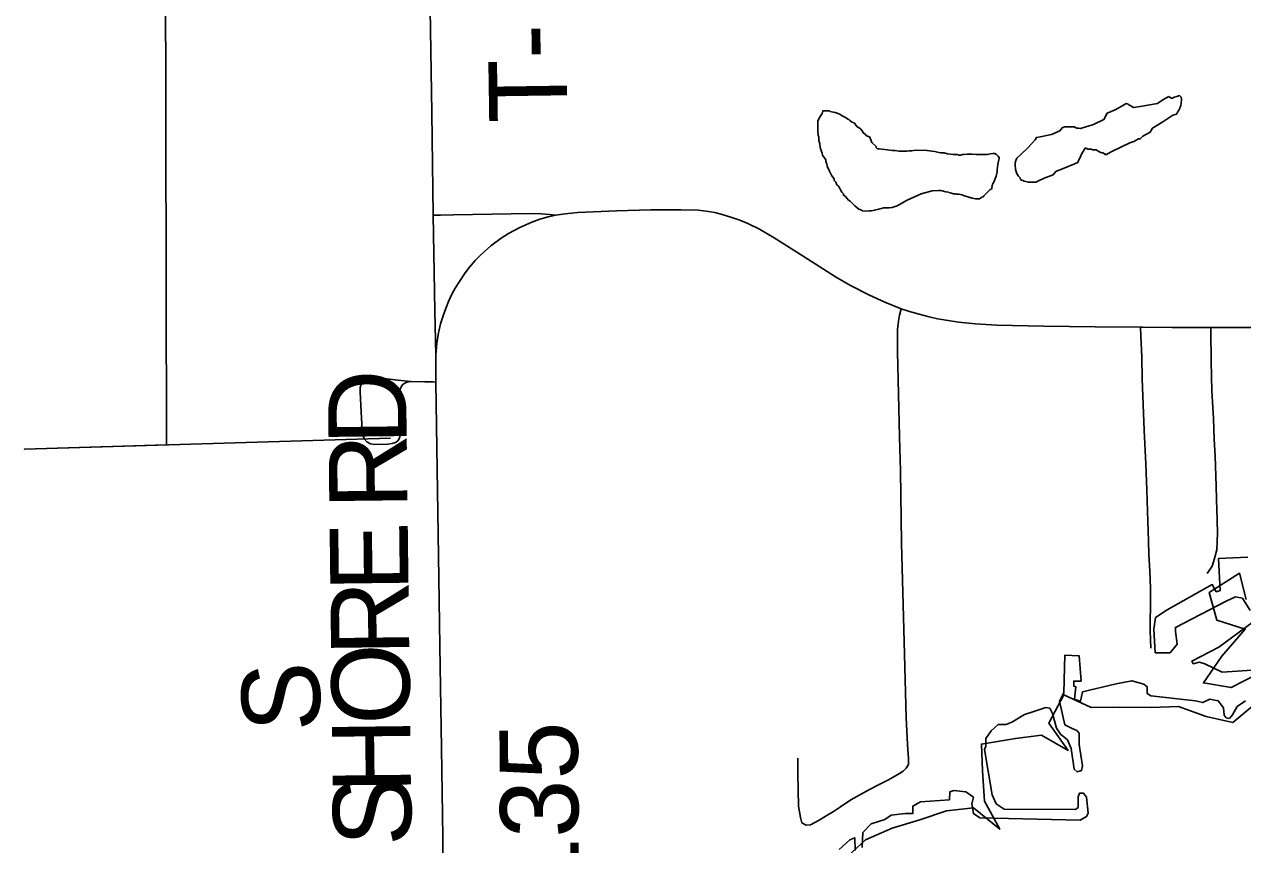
# Model space of a CAD drawing. Extents: x 0 to 34, y 0 to 22.
# Drawn here: x 8.1053 to 8.5479, y 18.1919 to 18.4901 of the extents above; entities that cross this region are included whole.
import ezdxf

# ---------------------------------------------------------------- set-up
doc = ezdxf.new("R2010")
doc.units = 0
for name, color, linetype in [('GM_X_Corporation', 7, 'Continuous'), ('GM_X_County_Road', 7, 'Continuous'), ('GM_X_County_Road_Text', 7, 'Continuous'), ('GM_X_Major_Lake', 7, 'Continuous'), ('GM_X_Minor_River', 7, 'Continuous'), ('GM_X_State_Route', 7, 'Continuous'), ('GM_X_Township_Road', 7, 'Continuous'), ('GM_X_Township_Road_Text', 7, 'Continuous')]:
    doc.layers.add(name, color=color, linetype=linetype)

msp = doc.modelspace()

# ---------------------------------------------------------------- linework, layer by layer
at = {"layer": 'GM_X_Corporation'}
for points in [[(8.55064, 18.27699), (8.54776, 18.28154), (8.54524, 18.28202), (8.54189, 18.28046), (8.52343, 18.27088), (8.52343, 18.26944), (8.52403, 18.26476), (8.52151, 18.26165), (8.51612, 18.26165), (8.51564, 18.27028), (8.51624, 18.27447), (8.52043, 18.27723), (8.53685, 18.28646), (8.53829, 18.28382), (8.53973, 18.2843), (8.53913, 18.29592), (8.5498, 18.2964)], [(8.55315, 18.25542), (8.54045, 18.25458), (8.5341, 18.25769), (8.53218, 18.25829), (8.5299, 18.25769), (8.52942, 18.25865), (8.53925, 18.26369), (8.55171, 18.27291)], [(8.4097, 18.19082), (8.40994, 18.19633), (8.41293, 18.19945), (8.41785, 18.20101), (8.42024, 18.20268), (8.42528, 18.20328), (8.42803, 18.20317), (8.42803, 18.20592), (8.43079, 18.20748), (8.44134, 18.2082), (8.44146, 18.21108), (8.4429, 18.21155), (8.44733, 18.21108), (8.45009, 18.20916), (8.44949, 18.20676), (8.45009, 18.20317), (8.45236, 18.20161), (8.48879, 18.20077), (8.49119, 18.20209), (8.49179, 18.2034), (8.49119, 18.20916), (8.49011, 18.21059), (8.48855, 18.21059), (8.48808, 18.20928), (8.48808, 18.20544), (8.48712, 18.20472), (8.46123, 18.20484), (8.45836, 18.20676), (8.45692, 18.20999), (8.45404, 18.22653), (8.45452, 18.22773), (8.45452, 18.23049), (8.45656, 18.23325), (8.45907, 18.23564), (8.46195, 18.23564), (8.46423, 18.2366), (8.46866, 18.23924), (8.4713, 18.24008), (8.47633, 18.24176), (8.47777, 18.24151), (8.47885, 18.23956), (8.48029, 18.2342), (8.48173, 18.23205), (8.48424, 18.23001), (8.48556, 18.22689), (8.48664, 18.21934), (8.48772, 18.21839), (8.48939, 18.21886), (8.48975, 18.22054), (8.48844, 18.22833), (8.48844, 18.23241), (8.4876, 18.23336), (8.48592, 18.23408), (8.48328, 18.2354), (8.48128, 18.24409), (8.48292, 18.24715), (8.48328, 18.26081), (8.48844, 18.26057), (8.48915, 18.25134), (8.48652, 18.25134), (8.48652, 18.24954), (8.48724, 18.24931), (8.48676, 18.24475), (8.4876, 18.24439), (8.48891, 18.24403), (8.48975, 18.24751), (8.50198, 18.25038), (8.50761, 18.25146), (8.51192, 18.25026), (8.51324, 18.24931), (8.51324, 18.24679), (8.51456, 18.24595), (8.53074, 18.24415), (8.53338, 18.24355), (8.53601, 18.24475), (8.53901, 18.24415), (8.54093, 18.24163), (8.54117, 18.239), (8.54189, 18.23804), (8.54309, 18.2378), (8.54416, 18.23912), (8.54584, 18.24211), (8.54896, 18.24415)], [(8.40131, 18.1901), (8.40514, 18.1937), (8.40694, 18.19442), (8.40706, 18.18974)]]:
    msp.add_lwpolyline(points, dxfattribs=at)
at = {"layer": 'GM_X_County_Road'}
for points in [[(8.25479, 18.36008), (8.25478, 18.36451), (8.25479, 18.36978)], [(8.2575, 18.17059), (8.25731, 18.19468), (8.25689, 18.22692), (8.25625, 18.26405), (8.25588, 18.28884), (8.25479, 18.36008)]]:
    msp.add_lwpolyline(points, dxfattribs=at)
at = {"layer": 'GM_X_Major_Lake'}
for points in [[(8.54918, 18.28107), (8.54671, 18.29057), (8.53571, 18.28354), (8.53855, 18.27347), (8.5488, 18.27024), (8.54026, 18.26037), (8.53362, 18.25068), (8.54368, 18.24897), (8.55317, 18.25391)], [(8.54918, 18.28107), (8.54671, 18.29057), (8.53571, 18.28354), (8.53855, 18.27347), (8.5488, 18.27024), (8.54026, 18.26037), (8.53362, 18.25068), (8.54368, 18.24897), (8.55317, 18.25391)], [(8.55374, 18.24422), (8.54425, 18.23625), (8.53457, 18.23853), (8.52452, 18.24213), (8.51465, 18.24175), (8.50326, 18.24194), (8.49283, 18.24175), (8.48296, 18.24631), (8.47746, 18.23605), (8.48448, 18.22618), (8.4748, 18.23168), (8.46532, 18.23054), (8.45298, 18.22845), (8.45336, 18.21877), (8.45412, 18.20775), (8.45962, 18.19749), (8.45014, 18.20528), (8.44027, 18.20414)], [(8.55374, 18.24422), (8.54425, 18.23625), (8.53457, 18.23853), (8.52452, 18.24213), (8.51465, 18.24175), (8.50326, 18.24194), (8.49283, 18.24175), (8.48296, 18.24631), (8.47746, 18.23605), (8.48448, 18.22618), (8.4748, 18.23168), (8.46532, 18.23054), (8.45298, 18.22845), (8.45336, 18.21877), (8.45412, 18.20775), (8.45962, 18.19749), (8.45014, 18.20528), (8.44027, 18.20414)], [(8.44027, 18.20414), (8.43059, 18.20091), (8.42054, 18.19787), (8.41086, 18.19369), (8.40137, 18.18495)]]:
    msp.add_lwpolyline(points, dxfattribs=at)
at = {"layer": 'GM_X_Minor_River'}
for points in [[(8.18599, 18.63264), (8.18437, 18.57885), (8.15649, 18.57188), (8.15692, 18.33718), (8.10529, 18.33561), (8.23835, 18.33965)], [(8.52105, 18.46387), (8.51883, 18.46259), (8.51692, 18.46128), (8.51064, 18.46023), (8.50817, 18.45989), (8.50723, 18.46047), (8.50648, 18.46086), (8.5063, 18.46105), (8.50554, 18.46126), (8.50458, 18.4607), (8.50153, 18.45903), (8.49866, 18.45775), (8.49749, 18.45548), (8.49367, 18.45364), (8.48891, 18.45219), (8.48816, 18.45239), (8.48759, 18.4524), (8.48665, 18.45279), (8.48323, 18.45284), (8.48228, 18.45247), (8.4815, 18.45134), (8.47845, 18.45006), (8.47427, 18.44917), (8.47294, 18.449), (8.47254, 18.44805), (8.46966, 18.44505), (8.46735, 18.44281), (8.46581, 18.4415), (8.46542, 18.44056), (8.46522, 18.4398), (8.46521, 18.43904), (8.46537, 18.43733), (8.46555, 18.43657), (8.46573, 18.43619), (8.46573, 18.436), (8.46647, 18.43485), (8.46703, 18.43427), (8.46721, 18.4337), (8.46853, 18.43311), (8.47004, 18.43271), (8.47289, 18.43267), (8.47346, 18.43304), (8.47575, 18.43414), (8.479, 18.43543), (8.47996, 18.43655), (8.48454, 18.43839), (8.48797, 18.43986), (8.48836, 18.4408), (8.48895, 18.44193), (8.48934, 18.44288), (8.4907, 18.44514), (8.49108, 18.44513), (8.49165, 18.44474), (8.49297, 18.44472), (8.49335, 18.44453), (8.49392, 18.44452), (8.49468, 18.44451), (8.49543, 18.44393), (8.49637, 18.44354), (8.49674, 18.44334), (8.49712, 18.44334), (8.49788, 18.44295), (8.49787, 18.44275), (8.49844, 18.44275), (8.49902, 18.44312), (8.50035, 18.44386), (8.50685, 18.44699), (8.50837, 18.44754), (8.51009, 18.44847), (8.51066, 18.44846), (8.51162, 18.4494), (8.5143, 18.45088), (8.51508, 18.45238), (8.5189, 18.45461), (8.52254, 18.45703), (8.52387, 18.45739), (8.52407, 18.45795), (8.52465, 18.45889), (8.52504, 18.45965), (8.52544, 18.46059), (8.52566, 18.46249), (8.52566, 18.46306), (8.52548, 18.46363), (8.52492, 18.46421), (8.52397, 18.46384), (8.52302, 18.46367), (8.52244, 18.46329), (8.52188, 18.4633), (8.52105, 18.46387)], [(8.52105, 18.46387), (8.51883, 18.46259), (8.51692, 18.46128), (8.51064, 18.46023), (8.50817, 18.45989), (8.50723, 18.46047), (8.50648, 18.46086), (8.5063, 18.46105), (8.50554, 18.46126), (8.50458, 18.4607), (8.50153, 18.45903), (8.49866, 18.45775), (8.49749, 18.45548), (8.49367, 18.45364), (8.48891, 18.45219), (8.48816, 18.45239), (8.48759, 18.4524), (8.48665, 18.45279), (8.48323, 18.45284), (8.48228, 18.45247), (8.4815, 18.45134), (8.47845, 18.45006), (8.47427, 18.44917), (8.47294, 18.449), (8.47254, 18.44805), (8.46966, 18.44505), (8.46735, 18.44281), (8.46581, 18.4415), (8.46542, 18.44056), (8.46522, 18.4398), (8.46521, 18.43904), (8.46537, 18.43733), (8.46555, 18.43657), (8.46573, 18.43619), (8.46573, 18.436), (8.46647, 18.43485), (8.46703, 18.43427), (8.46721, 18.4337), (8.46853, 18.43311), (8.47004, 18.43271), (8.47289, 18.43267), (8.47346, 18.43304), (8.47575, 18.43414), (8.479, 18.43543), (8.47996, 18.43655)], [(8.47996, 18.43655), (8.48454, 18.43839), (8.48797, 18.43986), (8.48836, 18.4408), (8.48895, 18.44193), (8.48934, 18.44288), (8.4907, 18.44514), (8.49108, 18.44513), (8.49165, 18.44474), (8.49297, 18.44472), (8.49335, 18.44453), (8.49392, 18.44452), (8.49468, 18.44451), (8.49543, 18.44393), (8.49637, 18.44354), (8.49674, 18.44334), (8.49712, 18.44334), (8.49788, 18.44295), (8.49787, 18.44275), (8.49844, 18.44275), (8.49902, 18.44312), (8.50035, 18.44386), (8.50685, 18.44699), (8.50837, 18.44754), (8.51009, 18.44847), (8.51066, 18.44846), (8.51162, 18.4494), (8.5143, 18.45088), (8.51508, 18.45238), (8.5189, 18.45461), (8.52254, 18.45703), (8.52387, 18.45739), (8.52407, 18.45795), (8.52465, 18.45889), (8.52504, 18.45965), (8.52544, 18.46059), (8.52566, 18.46249), (8.52566, 18.46306), (8.52548, 18.46363), (8.52492, 18.46421), (8.52397, 18.46384), (8.52302, 18.46367), (8.52244, 18.46329), (8.52188, 18.4633), (8.52105, 18.46387)], [(8.45521, 18.44279), (8.44953, 18.44287), (8.44782, 18.4429), (8.44668, 18.44272), (8.44611, 18.44273), (8.44535, 18.44255), (8.44478, 18.44256), (8.44422, 18.44276), (8.4427, 18.44278), (8.44062, 18.443), (8.43949, 18.44339), (8.43816, 18.44341), (8.43702, 18.44362), (8.43608, 18.44382), (8.43495, 18.44403), (8.43324, 18.44424), (8.42907, 18.4443), (8.42774, 18.44413), (8.42679, 18.44414), (8.42584, 18.44397), (8.423, 18.44401), (8.42168, 18.44422), (8.42054, 18.44423), (8.41884, 18.44445), (8.41581, 18.44487), (8.41524, 18.44488), (8.41468, 18.44527), (8.41468, 18.44565), (8.41319, 18.44719), (8.41246, 18.4491), (8.41114, 18.44968), (8.41058, 18.45026), (8.41002, 18.45065), (8.40983, 18.45122), (8.4089, 18.45218), (8.40777, 18.45296), (8.40684, 18.45411), (8.40572, 18.4547), (8.40515, 18.45509), (8.40478, 18.45547), (8.4044, 18.45567), (8.40384, 18.45605), (8.40233, 18.45684), (8.40158, 18.45742), (8.39989, 18.45801), (8.39913, 18.45821), (8.398, 18.45842), (8.39781, 18.45861), (8.3961, 18.45863), (8.39535, 18.45864), (8.39514, 18.4577), (8.39417, 18.45619), (8.39358, 18.45487), (8.39352, 18.45088), (8.39371, 18.45031), (8.3937, 18.44974), (8.39388, 18.44917), (8.39386, 18.44784), (8.39422, 18.4467), (8.39439, 18.44537), (8.39475, 18.44422), (8.39512, 18.44327), (8.3953, 18.4425), (8.39585, 18.44174), (8.39623, 18.44116), (8.39641, 18.44078), (8.3964, 18.44021), (8.39677, 18.43926), (8.39694, 18.43849), (8.39749, 18.43716), (8.39805, 18.4362), (8.3986, 18.43505), (8.39953, 18.4339), (8.39952, 18.43333), (8.40008, 18.43275), (8.40045, 18.4318), (8.40101, 18.43122), (8.40138, 18.43064), (8.40175, 18.42988), (8.4023, 18.42911), (8.40286, 18.42854), (8.40286, 18.42797), (8.40342, 18.42758), (8.40473, 18.42623), (8.40529, 18.42584), (8.40697, 18.42411), (8.40847, 18.42295), (8.40941, 18.42255), (8.40979, 18.42236), (8.4113, 18.42215), (8.41225, 18.42232), (8.41301, 18.42231), (8.41415, 18.42249), (8.41567, 18.42285), (8.41758, 18.42339), (8.41947, 18.42336)], [(8.45114, 18.4426), (8.45521, 18.44279), (8.44953, 18.44287), (8.44782, 18.4429), (8.44668, 18.44272), (8.44611, 18.44273), (8.44535, 18.44255), (8.44478, 18.44256), (8.44422, 18.44276), (8.4427, 18.44278), (8.44062, 18.443), (8.43949, 18.44339), (8.43816, 18.44341), (8.43702, 18.44362), (8.43608, 18.44382), (8.43495, 18.44403), (8.43324, 18.44424), (8.42907, 18.4443), (8.42774, 18.44413), (8.42679, 18.44414), (8.42584, 18.44397), (8.423, 18.44401), (8.42168, 18.44422), (8.42054, 18.44423), (8.41884, 18.44445), (8.41581, 18.44487), (8.41524, 18.44488), (8.41468, 18.44527), (8.41468, 18.44565), (8.41319, 18.44719), (8.41246, 18.4491), (8.41114, 18.44968), (8.41058, 18.45026), (8.41002, 18.45065), (8.40983, 18.45122), (8.4089, 18.45218), (8.40777, 18.45296), (8.40684, 18.45411), (8.40572, 18.4547), (8.40515, 18.45509), (8.40478, 18.45547), (8.4044, 18.45567), (8.40384, 18.45605), (8.40233, 18.45684), (8.40158, 18.45742), (8.39989, 18.45801), (8.39913, 18.45821), (8.398, 18.45842), (8.39781, 18.45861), (8.3961, 18.45863), (8.39535, 18.45864), (8.39514, 18.4577), (8.39417, 18.45619), (8.39358, 18.45487), (8.39352, 18.45088), (8.39371, 18.45031), (8.3937, 18.44974), (8.39388, 18.44917), (8.39386, 18.44784), (8.39422, 18.4467), (8.39439, 18.44537), (8.39475, 18.44422), (8.39512, 18.44327), (8.3953, 18.4425), (8.39585, 18.44174), (8.39623, 18.44116), (8.39641, 18.44078), (8.3964, 18.44021), (8.39677, 18.43926), (8.39694, 18.43849), (8.39749, 18.43716), (8.39805, 18.4362), (8.3986, 18.43505), (8.39953, 18.4339), (8.39952, 18.43333), (8.40008, 18.43275), (8.40045, 18.4318), (8.40101, 18.43122), (8.40138, 18.43064), (8.40175, 18.42988), (8.4023, 18.42911), (8.40286, 18.42854), (8.40286, 18.42797), (8.40342, 18.42758), (8.40473, 18.42623), (8.40529, 18.42584), (8.40697, 18.42411), (8.40847, 18.42295), (8.40941, 18.42255), (8.40979, 18.42236), (8.4113, 18.42215), (8.41225, 18.42232), (8.41301, 18.42231), (8.41415, 18.42249), (8.41567, 18.42285), (8.41758, 18.42339), (8.41947, 18.42336)], [(8.41947, 18.42336), (8.42061, 18.42354), (8.42233, 18.42408), (8.42596, 18.42612), (8.43111, 18.42851), (8.43511, 18.4296), (8.43739, 18.42975), (8.43815, 18.42974), (8.43871, 18.42954), (8.44004, 18.42915), (8.44098, 18.42913), (8.44117, 18.42894), (8.44211, 18.42874), (8.44287, 18.42854), (8.44344, 18.42853), (8.44381, 18.42833), (8.44495, 18.42832), (8.4459, 18.42811), (8.44646, 18.42792), (8.44835, 18.42732), (8.44854, 18.42713), (8.44892, 18.42712), (8.44967, 18.42692), (8.4508, 18.42671), (8.45232, 18.42669), (8.45309, 18.42725), (8.45366, 18.42743), (8.45386, 18.42781), (8.45616, 18.43006), (8.45673, 18.43024), (8.45674, 18.43081), (8.45695, 18.43194), (8.45753, 18.4327), (8.45832, 18.43496), (8.45872, 18.43648), (8.45873, 18.43723), (8.45895, 18.43913), (8.45916, 18.44046), (8.45935, 18.44064), (8.45937, 18.44159), (8.459, 18.44217), (8.45844, 18.44275), (8.45787, 18.44313), (8.45711, 18.44314), (8.45616, 18.44297), (8.45521, 18.44279)]]:
    msp.add_lwpolyline(points, dxfattribs=at)
at = {"layer": 'GM_X_State_Route'}
msp.add_lwpolyline([(8.55772, 18.37993), (8.53627, 18.37991), (8.52231, 18.3799), (8.51144, 18.38004), (8.51078, 18.38004), (8.49433, 18.38013), (8.47569, 18.38037), (8.4586, 18.38079), (8.45086, 18.38123), (8.44469, 18.38182), (8.44011, 18.3825), (8.43697, 18.3831), (8.43404, 18.38375), (8.43038, 18.38468), (8.42679, 18.38574), (8.42385, 18.38672), (8.41791, 18.38906), (8.41226, 18.39163), (8.40539, 18.3952), (8.40001, 18.39828), (8.38693, 18.40665), (8.37771, 18.41246), (8.37232, 18.4156), (8.36813, 18.41772), (8.36523, 18.41892), (8.36233, 18.4199), (8.35881, 18.42098), (8.3561, 18.42166), (8.35294, 18.4222), (8.3501, 18.42251), (8.34373, 18.42272), (8.33283, 18.42272), (8.3204, 18.42236), (8.30641, 18.4217), (8.30174, 18.42127), (8.29835, 18.42072), (8.29559, 18.42011), (8.29257, 18.41924), (8.28962, 18.41818), (8.28531, 18.41629), (8.28119, 18.41404), (8.27855, 18.41234), (8.27478, 18.40953), (8.27123, 18.40644), (8.26902, 18.40421), (8.26699, 18.40181), (8.26543, 18.39971), (8.26331, 18.39662), (8.26185, 18.39418), (8.26064, 18.39196), (8.25939, 18.3893), (8.25852, 18.38711), (8.25738, 18.38415), (8.2565, 18.38118), (8.25577, 18.37796), (8.25516, 18.37422), (8.25479, 18.36978)], dxfattribs=at)
at = {"layer": 'GM_X_Township_Road'}
for points in [[(8.25381, 18.4207), (8.25335, 18.45797), (8.25249, 18.51077), (8.25217, 18.52319), (8.25219, 18.52784), (8.25145, 18.57598), (8.25088, 18.61014), (8.24998, 18.65828), (8.24985, 18.66722)], [(8.25381, 18.4207), (8.25644, 18.42076), (8.26114, 18.42082), (8.28901, 18.42138), (8.29305, 18.4212), (8.29605, 18.42097), (8.29835, 18.42072)], [(8.25479, 18.36978), (8.2544, 18.3859), (8.25381, 18.4207)], [(8.38623, 18.22332), (8.38623, 18.21774), (8.38658, 18.20591), (8.38719, 18.20182), (8.38775, 18.19981), (8.38928, 18.19904), (8.39084, 18.19912), (8.39241, 18.19991), (8.39398, 18.20078), (8.39655, 18.20236), (8.3992, 18.20392), (8.40174, 18.20564), (8.40557, 18.20823), (8.41229, 18.21199), (8.41505, 18.21339), (8.41919, 18.21544), (8.42323, 18.21775), (8.42451, 18.21864), (8.42566, 18.2197), (8.42646, 18.22098), (8.42651, 18.22306), (8.42608, 18.22828), (8.42564, 18.23811), (8.42545, 18.2472), (8.42504, 18.26114), (8.42393, 18.30144), (8.42359, 18.32778), (8.42326, 18.34017), (8.42289, 18.35567), (8.4225, 18.37117), (8.42246, 18.37581), (8.42251, 18.37918), (8.42284, 18.38224), (8.4232, 18.3844), (8.42385, 18.38672)], [(8.51457, 18.26333), (8.51431, 18.26959), (8.51444, 18.28208), (8.51435, 18.28518), (8.51414, 18.29135), (8.51385, 18.29752), (8.51367, 18.30218), (8.51334, 18.31307), (8.51306, 18.32085), (8.51266, 18.33017), (8.51206, 18.34258), (8.51182, 18.34881), (8.51143, 18.36129), (8.5112, 18.36908), (8.5109, 18.37686), (8.51078, 18.38004)], [(8.535, 18.29049), (8.53674, 18.29319), (8.53769, 18.29597), (8.53848, 18.29911), (8.53865, 18.30224), (8.53874, 18.30502), (8.53856, 18.30998), (8.53839, 18.31738), (8.5383, 18.32234), (8.53789, 18.33314), (8.53753, 18.33932), (8.53725, 18.34687), (8.53665, 18.35688), (8.53647, 18.36758), (8.53629, 18.37828), (8.53627, 18.37991)], [(8.24573, 18.36021), (8.24099, 18.36078), (8.23498, 18.36151), (8.23218, 18.36169), (8.23075, 18.36159), (8.22965, 18.36129), (8.22871, 18.36071), (8.22776, 18.35961), (8.22729, 18.35814), (8.22726, 18.35655), (8.22748, 18.35149), (8.22802, 18.34239), (8.22821, 18.34083), (8.22873, 18.33939), (8.22969, 18.3383), (8.23102, 18.33764), (8.23258, 18.33741), (8.23735, 18.3375), (8.23892, 18.33767), (8.24012, 18.3381), (8.24091, 18.3387), (8.24141, 18.3394), (8.24168, 18.34013), (8.24185, 18.3411), (8.24194, 18.3424), (8.2416, 18.35497), (8.24164, 18.35655), (8.24181, 18.35752), (8.24214, 18.35832), (8.24261, 18.35906), (8.24321, 18.35959), (8.24418, 18.35998), (8.24573, 18.36021)], [(8.24573, 18.36021), (8.25077, 18.36019), (8.25386, 18.36009), (8.25479, 18.36008)]]:
    msp.add_lwpolyline(points, dxfattribs=at)

# ---------------------------------------------------------------- texts
at = {"layer": 'GM_X_County_Road_Text'}
for s, height, rotation, p in [('D', 0.02841, 90.6922, (8.24423, 18.33733)), ('R', 0.02841, 90.6931, (8.24451, 18.314)), ('E', 0.02841, 90.6931, (8.24487, 18.284)), ('R', 0.02841, 90.6872, (8.24515, 18.26066)), ('O', 0.02841, 90.6922, (8.24545, 18.23567)), ('S', 0.02841, 91.2447, (8.21294, 18.23326)), ('H', 0.02841, 90.6922, (8.24576, 18.21067)), ('C-135', 0.028409, 90.5458, (8.30723, 18.13327)), ('S', 0.02841, 90.692, (8.24599, 18.1915))]:
    msp.add_text(s, height=height, rotation=rotation, dxfattribs=at).set_placement(p)
at = {"layer": 'GM_X_Township_Road_Text'}
msp.add_text('T-140', height=0.028409, rotation=90.8452, dxfattribs=at).set_placement((8.30258, 18.45448))

doc.saveas('drawing.dxf')
